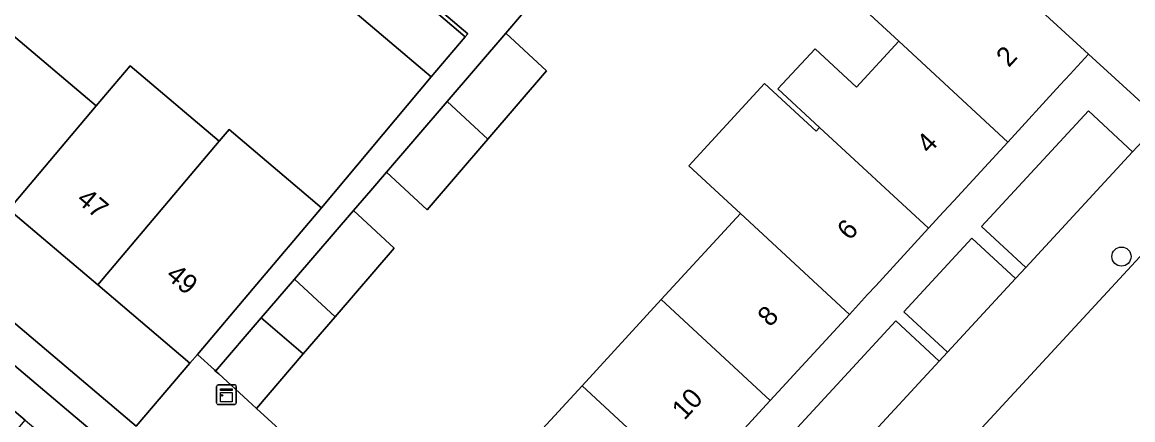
# Model space of a CAD drawing. Extents: x 162523 to 163266, y 381230 to 382050.
# Drawn here: x 163030.7 to 163087.5, y 381549.1 to 381569.4 of the extents above; entities that cross this region are included whole.
import ezdxf

# ---------------------------------------------------------------- set-up
doc = ezdxf.new("R2010")
doc.units = 0
for name, color, linetype in [('IMGEO_Boom', 7, 'Continuous'), ('IMGEO_Erf', 7, 'Continuous'), ('IMGEO_Groenvoorziening', 7, 'Continuous'), ('IMGEO_Kast', 7, 'Continuous'), ('IMGEO_Pand', 7, 'Continuous'), ('IMGEO_Pand_nummerreeks', 7, 'Continuous'), ('IMGEO_Parkeervlak_open', 7, 'Continuous'), ('IMGEO_Rijbaan_lokaal_open', 7, 'Continuous'), ('IMGEO_Voetpad_open', 7, 'Continuous')]:
    doc.layers.add(name, color=color, linetype=linetype)

msp = doc.modelspace()

# ---------------------------------------------------------------- linework, layer by layer
at = {"layer": 'IMGEO_Boom'}
msp.add_circle((163086.898, 381557.441), 0.489, dxfattribs=at)
at = {"layer": 'IMGEO_Erf'}
msp.add_lwpolyline([(162981.863, 381595.134), (163000, 381579.765), (163036.569, 381548.778), (163039.317, 381552), (163034.602, 381555.997), (163030.056, 381559.851), (163025.51, 381563.705), (163020.964, 381567.558), (163016.417, 381571.413), (163011.871, 381575.266), (163007.325, 381579.12), (163002.778, 381582.975), (163000, 381585.33), (162998.232, 381586.828), (162993.686, 381590.682), (162989.14, 381594.536), (162984.611, 381598.375)], close=True, dxfattribs=at)
for points in [[(163029.979, 381568.985), (163034.526, 381565.131), (163036.258, 381567.177), (163040.807, 381563.328), (163041.322, 381563.936), (163046.042, 381559.934), (163051.635, 381566.617), (163046.97, 381570.588), (163043.449, 381573.586), (163045.187, 381575.64), (163048.709, 381572.642), (163053.379, 381568.666), (163053.502, 381568.81), (163048.831, 381572.787), (163044.291, 381576.652), (163039.751, 381580.517), (163035.21, 381584.382), (163030.67, 381588.247)], [(163055.297, 381546.452), (163059.343, 381550.848), (163063.388, 381555.244), (163067.433, 381559.64), (163064.803, 381562.072), (163068.673, 381566.276), (163071.308, 381563.85), (163071.479, 381564.035), (163069.354, 381566), (163071.251, 381568.051), (163073.371, 381566.091), (163075.524, 381568.431), (163072.353, 381571.364)], [(163056.348, 381569.895), (163055.444, 381568.843), (163057.523, 381566.921), (163054.528, 381563.437), (163051.431, 381559.834), (163049.353, 381561.756), (163048.55, 381560.821), (163047.674, 381559.801), (163049.751, 381557.879), (163046.729, 381554.362), (163045.106, 381552.473), (163042.716, 381549.691), (163050.067, 381542.984)], [(163087.943, 381565.297), (163085.215, 381567.768), (163084.275, 381566.746), (163083.775, 381566.203), (163081.09, 381563.283), (163078.336, 381560.289), (163077.812, 381559.72), (163077.046, 381558.887), (163074.346, 381555.952), (163073.929, 381555.499), (163073.001, 381554.49), (163068.957, 381550.093), (163066.296, 381547.2), (163065.809, 381546.67), (163064.913, 381545.696), (163064.153, 381544.87), (163063.644, 381544.317), (163060.868, 381541.299), (163058.248, 381538.45), (163057.792, 381537.955), (163056.761, 381536.834), (163059.443, 381534.236)], [(163066.358, 381544.36), (163067.255, 381545.329), (163069.447, 381543.306), (163069.938, 381543.831), (163067.722, 381545.881), (163075.377, 381554.158), (163077.594, 381552.111), (163078.012, 381552.563), (163075.786, 381554.618), (163079.263, 381558.379), (163081.488, 381556.322), (163082.012, 381556.889), (163079.758, 381558.974), (163085.213, 381564.874), (163087.467, 381562.789), (163087.968, 381563.331), (163088.083, 381563.455)]]:
    msp.add_lwpolyline(points, dxfattribs=at)
at = {"layer": 'IMGEO_Groenvoorziening'}
for points in [[(163087.467, 381562.789), (163085.213, 381564.874), (163079.758, 381558.974), (163082.012, 381556.889)], [(163081.488, 381556.322), (163079.263, 381558.379), (163075.786, 381554.618), (163078.012, 381552.563)], [(163077.594, 381552.111), (163075.377, 381554.158), (163067.722, 381545.881), (163069.938, 381543.831)]]:
    msp.add_lwpolyline(points, close=True, dxfattribs=at)
at = {"layer": 'IMGEO_Kast'}
for p, q in [((163040.677, 381549.968), (163040.677, 381550.809)), ((163040.677, 381550.809), (163040.677, 381549.968)), ((163040.752, 381550.893), (163041.593, 381550.893)), ((163041.593, 381550.893), (163040.752, 381550.893)), ((163041.677, 381550.818), (163041.677, 381549.977)), ((163041.677, 381549.977), (163041.677, 381550.818)), ((163041.602, 381549.893), (163040.761, 381549.893)), ((163040.761, 381549.893), (163041.602, 381549.893))]:
    msp.add_line(p, q, dxfattribs=at)
for points in [[(163040.872, 381550.683), (163041.472, 381550.683), (163041.472, 381550.598), (163040.872, 381550.598), (163040.872, 381550.683)], [(163040.872, 381550.508), (163041.472, 381550.508), (163041.472, 381550.019), (163040.872, 381550.019), (163040.872, 381550.508)]]:
    msp.add_lwpolyline(points, dxfattribs=at)
msp.add_circle((163040.956, 381550.357), 0.0377, dxfattribs=at)
for centre, start, end in [((163040.755, 381550.815), 92.4484, 184.2845), ((163040.755, 381550.815), 92.4484, 184.2845), ((163041.599, 381550.815), 2.4484, 94.2845), ((163041.599, 381550.815), 2.4484, 94.2845), ((163040.755, 381549.971), 182.4484, 274.2845), ((163040.755, 381549.971), 182.4484, 274.2845), ((163041.599, 381549.971), 272.4484, 4.2845), ((163041.599, 381549.971), 272.4484, 4.2845)]:
    msp.add_arc(centre, 0.0779, start, end, dxfattribs=at)
at = {"layer": 'IMGEO_Pand'}
for points in [[(163075.524, 381568.431), (163081.09, 381563.283), (163083.775, 381566.203), (163084.275, 381566.746), (163085.215, 381567.768), (163079.637, 381572.9), (163076.458, 381575.825), (163072.353, 381571.364)], [(163048.709, 381572.642), (163046.97, 381570.588), (163051.635, 381566.617), (163053.379, 381568.666)], [(163029.979, 381568.985), (163025.51, 381563.705), (163030.056, 381559.851), (163034.526, 381565.131)], [(163057.523, 381566.921), (163055.444, 381568.843), (163052.45, 381565.359), (163054.528, 381563.437)], [(163075.524, 381568.431), (163073.371, 381566.091), (163071.251, 381568.051), (163069.354, 381566), (163071.479, 381564.035), (163077.046, 381558.887), (163077.812, 381559.72), (163078.336, 381560.289), (163081.09, 381563.283)], [(163034.602, 381555.997), (163040.807, 381563.328), (163036.258, 381567.177), (163034.526, 381565.131), (163030.056, 381559.851)], [(163071.479, 381564.035), (163071.308, 381563.85), (163068.673, 381566.276), (163064.803, 381562.072), (163067.433, 381559.64), (163073.001, 381554.49), (163073.929, 381555.499), (163074.346, 381555.952), (163077.046, 381558.887)], [(163054.528, 381563.437), (163052.45, 381565.359), (163049.353, 381561.756), (163051.431, 381559.834)], [(163034.602, 381555.997), (163039.317, 381552), (163039.698, 381552.449), (163042.551, 381555.815), (163046.042, 381559.934), (163041.322, 381563.936), (163040.807, 381563.328)], [(163049.751, 381557.879), (163047.674, 381559.801), (163044.651, 381556.284), (163046.729, 381554.362)], [(163073.001, 381554.49), (163067.433, 381559.64), (163063.388, 381555.244), (163068.957, 381550.093)], [(163044.651, 381556.284), (163042.96, 381554.317), (163045.106, 381552.473), (163046.729, 381554.362)], [(163064.913, 381545.696), (163065.809, 381546.67), (163066.296, 381547.2), (163068.957, 381550.093), (163063.388, 381555.244), (163059.343, 381550.848)], [(163045.106, 381552.473), (163042.96, 381554.317), (163040.625, 381551.601), (163040.789, 381551.45), (163042.266, 381550.102), (163042.716, 381549.691)], [(163064.913, 381545.696), (163059.343, 381550.848), (163055.297, 381546.452), (163060.868, 381541.299), (163063.644, 381544.317), (163064.153, 381544.87)]]:
    msp.add_lwpolyline(points, close=True, dxfattribs=at)
at = {"layer": 'IMGEO_Parkeervlak_open'}
for points in [[(162980.91, 381591.262), (162995.604, 381578.864), (162997.752, 381577.051), (163000, 381575.154), (163012.294, 381564.78), (163028.675, 381550.968), (163030.892, 381549.099), (163051.36, 381531.841)], [(163050.423, 381534.936), (163041.176, 381542.758), (163038.305, 381545.169), (163015.44, 381564.469)]]:
    msp.add_lwpolyline(points, dxfattribs=at)
at = {"layer": 'IMGEO_Rijbaan_lokaal_open'}
msp.add_lwpolyline([(163095.231, 381556.507), (163095.794, 381557.097), (163093.568, 381559.16), (163091.341, 381561.224), (163062.628, 381530.156)], dxfattribs=at)
msp.add_lwpolyline([(163025.989, 381547.783), (163028.203, 381545.91), (163030.892, 381549.099), (163028.675, 381550.968)], close=True, dxfattribs=at)
at = {"layer": 'IMGEO_Voetpad_open'}
for points in [[(163000, 381644.529), (163000.523, 381644.317), (163007.344, 381638.581), (163011.124, 381635.401), (163014.093, 381632.903), (163014.757, 381633.658), (163035.384, 381616.107), (163069.377, 381587.184), (163068.742, 381586.409), (163066.867, 381584.206), (163067.892, 381583.334), (163072.717, 381579.194), (163076.458, 381575.825), (163079.637, 381572.9), (163085.215, 381567.768), (163087.943, 381565.297)], [(163055.845, 381528.54), (163059.443, 381534.236), (163056.761, 381536.834), (163051.175, 381541.973), (163050.067, 381542.984), (163042.716, 381549.691), (163042.266, 381550.102), (163040.789, 381551.45), (163040.625, 381551.601), (163040.564, 381551.656), (163039.698, 381552.449), (163039.317, 381552), (163036.569, 381548.778), (163000, 381579.765)], [(163048.831, 381572.787), (163053.502, 381568.81), (163053.379, 381568.666), (163051.635, 381566.617), (163046.042, 381559.934), (163042.551, 381555.815), (163039.698, 381552.449), (163040.564, 381551.656), (163040.625, 381551.601), (163042.96, 381554.317), (163044.651, 381556.284), (163047.674, 381559.801), (163048.55, 381560.821), (163049.353, 381561.756), (163052.45, 381565.359), (163055.444, 381568.843), (163056.348, 381569.895)], [(163015.44, 381564.469), (163038.305, 381545.169), (163041.176, 381542.758), (163050.423, 381534.936)], [(163088.083, 381563.455), (163087.968, 381563.331), (163087.467, 381562.789), (163082.012, 381556.889), (163081.488, 381556.322), (163078.012, 381552.563), (163077.594, 381552.111), (163069.938, 381543.831), (163069.447, 381543.306), (163068.55, 381542.332), (163064.525, 381537.917), (163061.922, 381535.053), (163061.469, 381534.555), (163061.243, 381534.306)], [(163062.628, 381530.156), (163091.341, 381561.224)]]:
    msp.add_lwpolyline(points, dxfattribs=at)

# ---------------------------------------------------------------- texts
at = {"layer": 'IMGEO_Pand_nummerreeks'}
for s, rotation, p in [('2', 47.3912, (163081.14, 381567.061)), ('4', 47.3912, (163077.077, 381562.644)), ('47', 319.7116, (163033.469, 381560.262)), ('6', 47.3893, (163073.011, 381558.223)), ('49', 319.7116, (163038.034, 381556.392)), ('8', 47.3912, (163068.95, 381553.807)), ('10', 47.3912, (163064.573, 381549.049))]:
    msp.add_text(s, height=1, rotation=rotation, dxfattribs=at).set_placement(p)

doc.saveas('drawing.dxf')
